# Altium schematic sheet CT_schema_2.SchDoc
size 276 x 169 mm
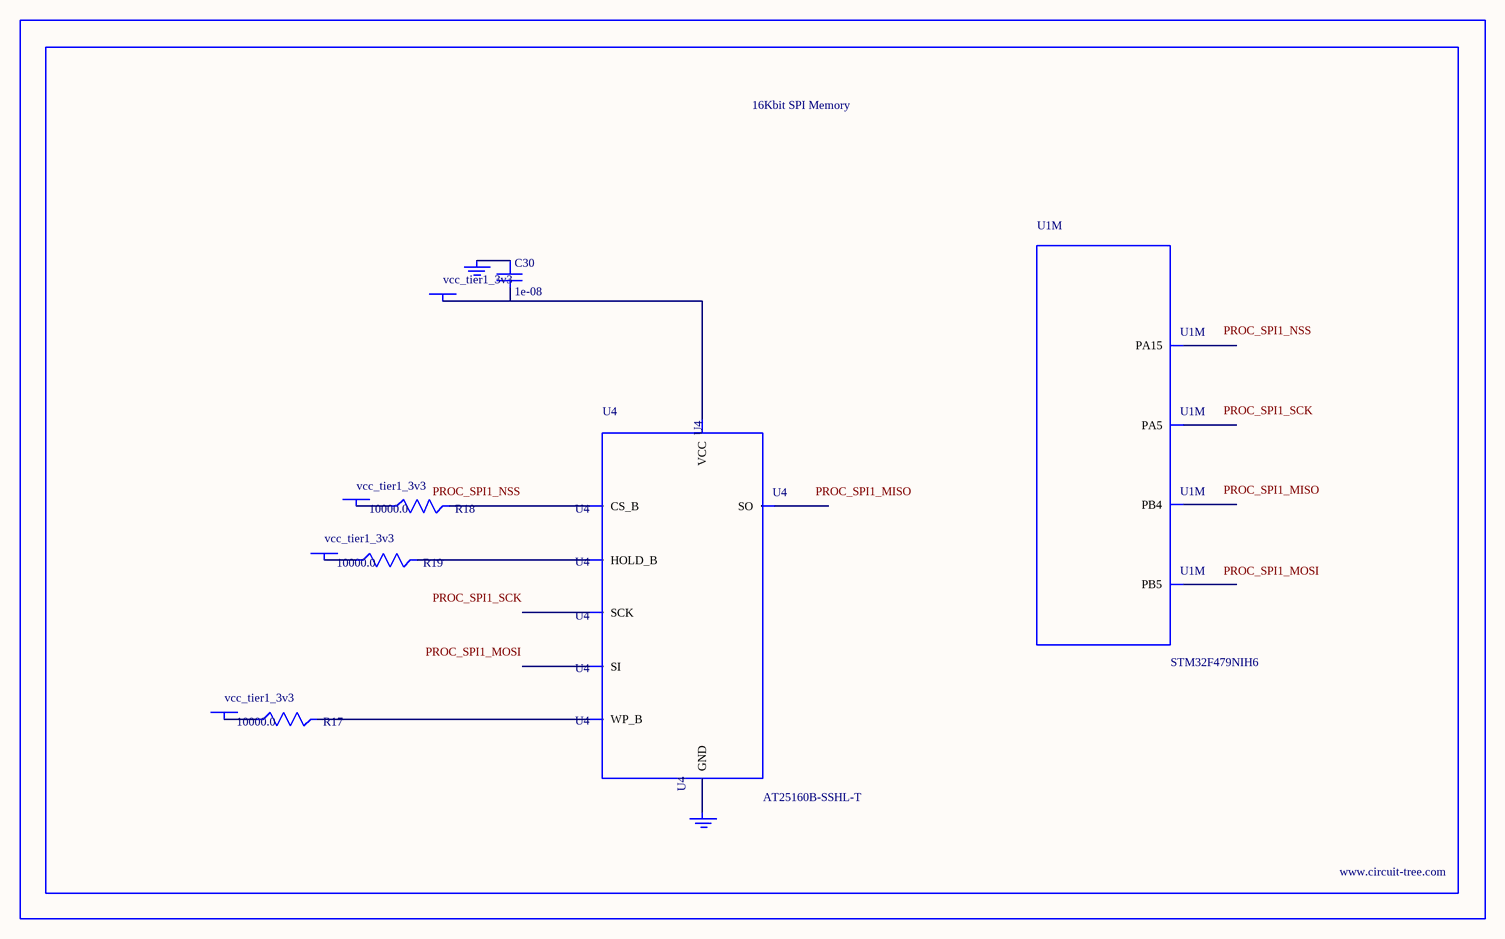
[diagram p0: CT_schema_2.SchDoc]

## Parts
BORDER1  (no value)
C30  1e-08  [C0402]
GND_INSTANCE_1_0  (no value)
GND_INSTANCE_1_1  (no value)
POWER_INSTANCE_1_0  vcc_tier1_3v3
POWER_INSTANCE_1_1  vcc_tier1_3v3
POWER_INSTANCE_1_2  vcc_tier1_3v3
POWER_INSTANCE_1_3  vcc_tier1_3v3
R17  10000.0  [R0603]
R18  10000.0  [R0603]
R19  10000.0  [R0603]
U1  STM32F479NIH6  [TFBGA216]  (part M of 17)
U4  AT25160B-SSHL-T  [SOIC-8]

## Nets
NetC30_1: C30.1 GND_INSTANCE_1_0.0(GND)
NetC30_2: C30.2 POWER_INSTANCE_1_3.0(PWR) U4.8(VCC)
NetGND_INSTANCE_1_1_0: GND_INSTANCE_1_1.0(GND) U4.4(GND)
NetPOWER_INSTANCE_1_0_0: POWER_INSTANCE_1_0.0(PWR) R18.1
NetPOWER_INSTANCE_1_1_0: POWER_INSTANCE_1_1.0(PWR) R17.1
NetPOWER_INSTANCE_1_2_0: POWER_INSTANCE_1_2.0(PWR) R19.1
NetR17_2: R17.2 U4.3(WP_B)
NetR18_2: R18.2 U4.1(CS_B)
NetR19_2: R19.2 U4.7(HOLD_B)

Not connected (* = marked no-connect by the designer): U1 A8(PB5) A9(PB4) A13(PA15) P4(PA5); U4 2(SO) 5(SI) 6(SCK)

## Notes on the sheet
- Labels drawn without touching a wire or pin: PROC_SPI1_MISO, PROC_SPI1_MOSI, PROC_SPI1_NSS, PROC_SPI1_SCK

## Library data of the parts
BORDER1 = BORDER_PAGE1
C30 = C0402C103K3RAC
GND_INSTANCE_1_0 GND_INSTANCE_1_1 = GND
POWER_INSTANCE_1_0-POWER_INSTANCE_1_3 = PWR
R17-R19 = RC0603JR-0710KL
